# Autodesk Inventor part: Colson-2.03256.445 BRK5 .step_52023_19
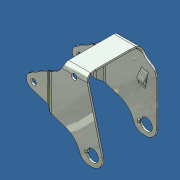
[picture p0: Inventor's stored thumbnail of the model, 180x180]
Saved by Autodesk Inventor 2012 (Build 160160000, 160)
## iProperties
Created: 2010-10
Part Number: Colson-2.03256.445 BRK5 .step_52023_19
Document SubType Name: Modeling
Designer: Administrator
Density: 7.85 g/cm^3
Material: Steel
Mass: 73.1668 g
Surface Area: 132.974 cm^2
Volume: 9.32061 cm^3
Author: Administrator
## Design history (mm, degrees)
feature "Base1"
body "Solid1"
